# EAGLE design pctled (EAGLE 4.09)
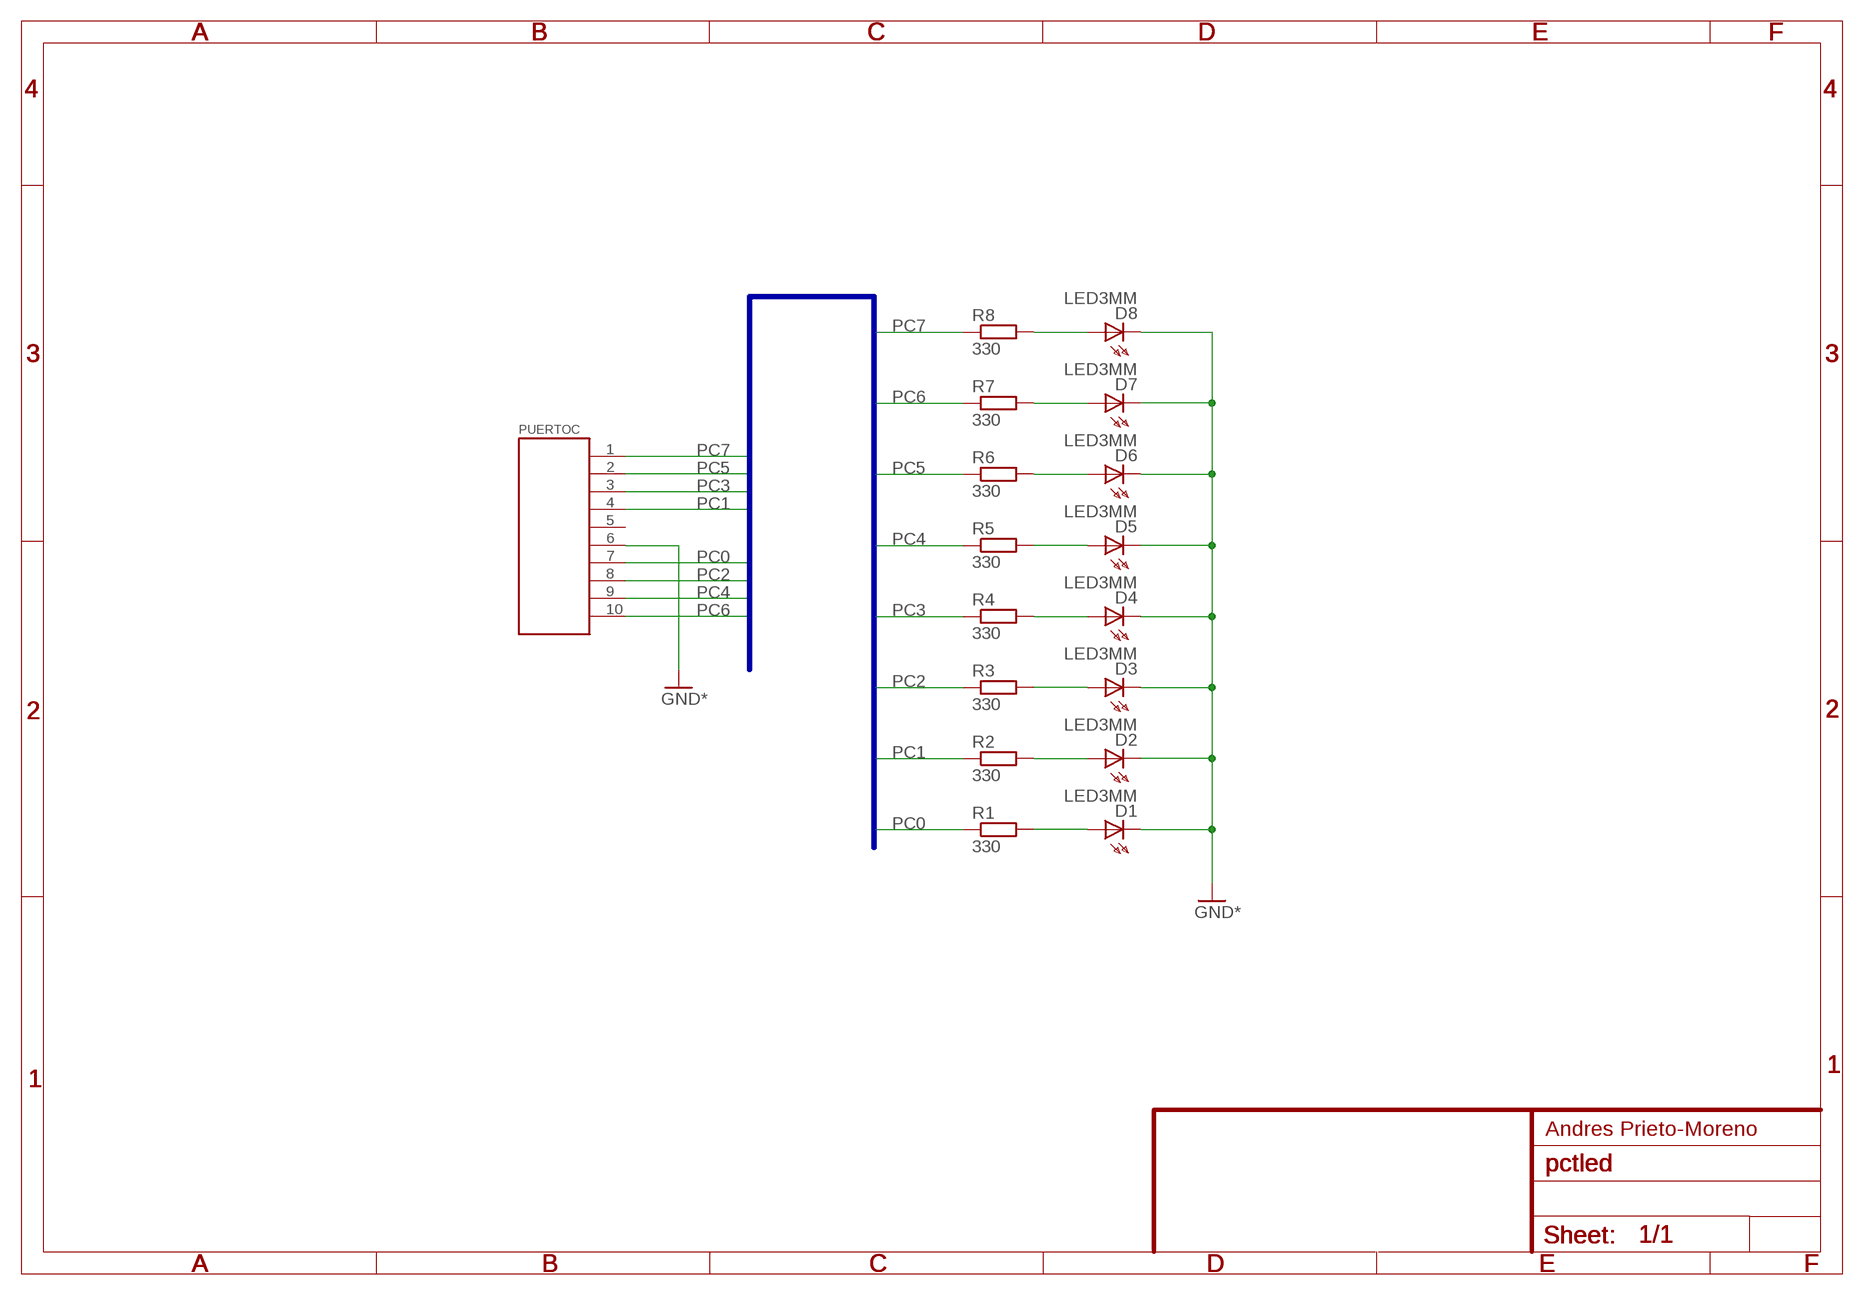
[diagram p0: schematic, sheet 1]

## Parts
D1  LED3MM  [LED3MM]
D2  LED3MM  [LED3MM]
D3  LED3MM  [LED3MM]
D4  LED3MM  [LED3MM]
D5  LED3MM  [LED3MM]
D6  LED3MM  [LED3MM]
D7  LED3MM  [LED3MM]
D8  LED3MM  [LED3MM]
PUERTOC  CTCONCTCON  [CTCON]
R1  330  R-EU_0207/10  [0207/10]
R2  330  R-EU_0207/10  [0207/10]
R3  330  R-EU_0207/10  [0207/10]
R4  330  R-EU_0207/10  [0207/10]
R5  330  R-EU_0207/10  [0207/10]
R6  330  R-EU_0207/10  [0207/10]
R7  330  R-EU_0207/10  [0207/10]
R8  330  R-EU_0207/10  [0207/10]

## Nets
GND: D1.K(C) D2.K(C) D3.K(C) D4.K(C) D5.K(C) D6.K(C) D7.K(C) D8.K(C) PUERTOC.6 ; supply symbol labelled GND*
N$1: D8.A R8.2
N$2: D7.A R7.2
N$3: D6.A R6.2
N$4: D5.A R5.2
N$5: D4.A R4.2
N$6: D3.A R3.2
N$7: D2.A R2.2
N$8: D1.A R1.2
PC0: PUERTOC.7 R1.1
PC1: PUERTOC.4 R2.1
PC2: PUERTOC.8 R3.1
PC3: PUERTOC.3 R4.1
PC4: PUERTOC.9 R5.1
PC5: PUERTOC.2 R6.1
PC6: PUERTOC.10 R7.1
PC7: PUERTOC.1 R8.1
Unconnected: PUERTOC.5

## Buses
BUSC:PC[0..7]

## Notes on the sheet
- Andres Prieto-Moreno

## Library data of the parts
D1-D8 = led:LED3MM: LED
PUERTOC = custom:CTCON: Conector compatible CT
R1-R8 = rcl:R-EU_: RESISTOR, European symbol

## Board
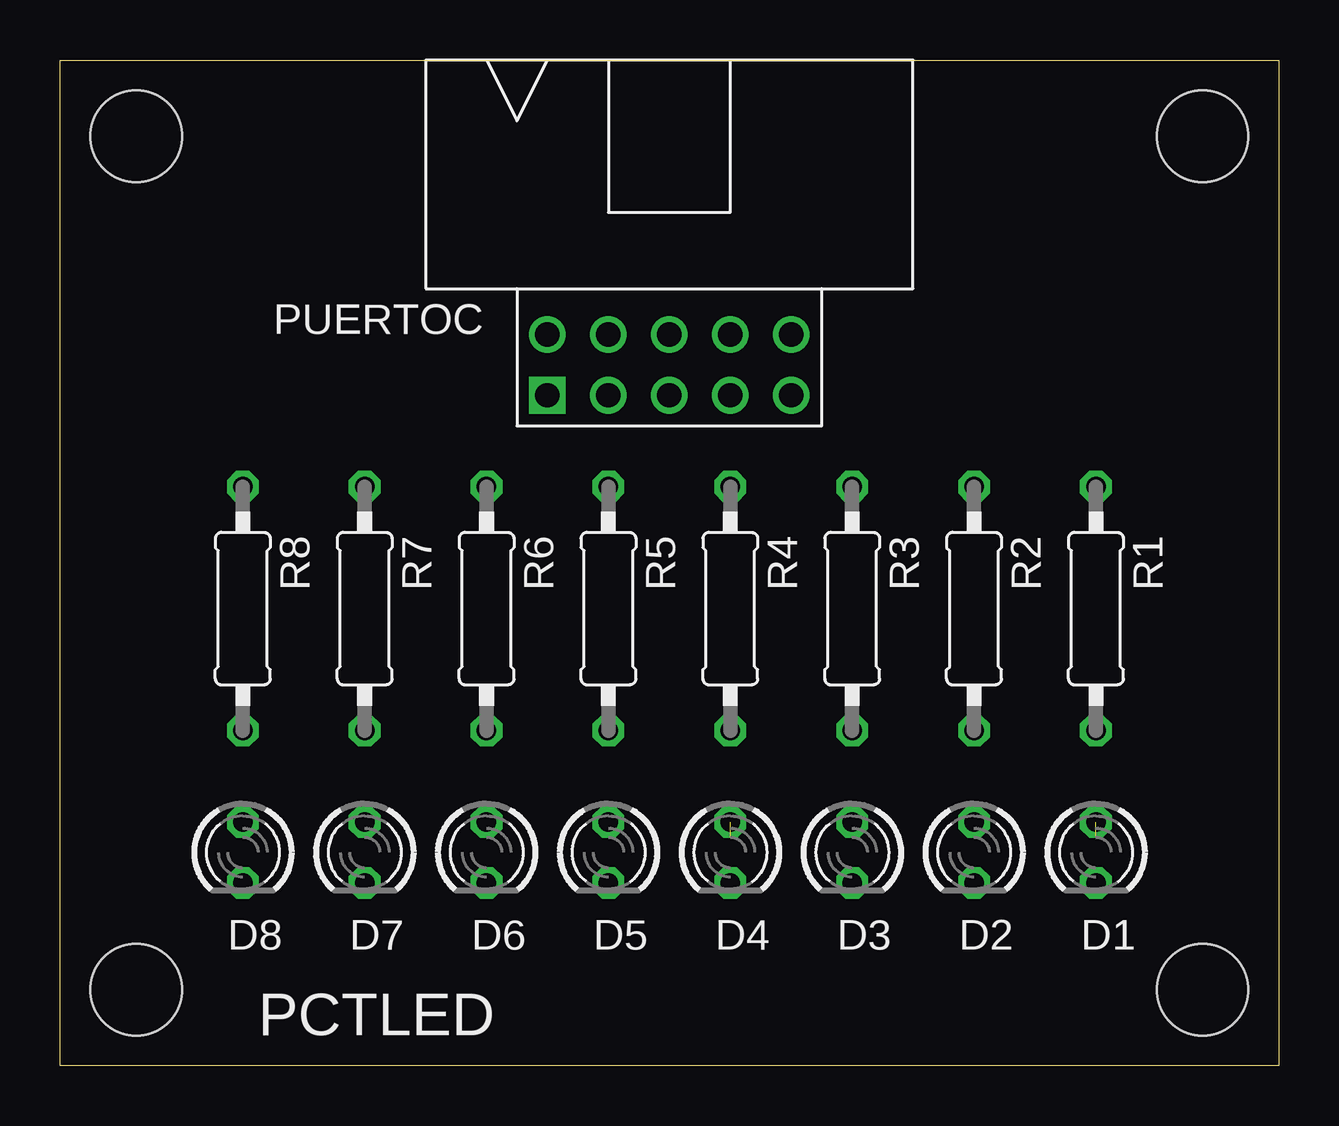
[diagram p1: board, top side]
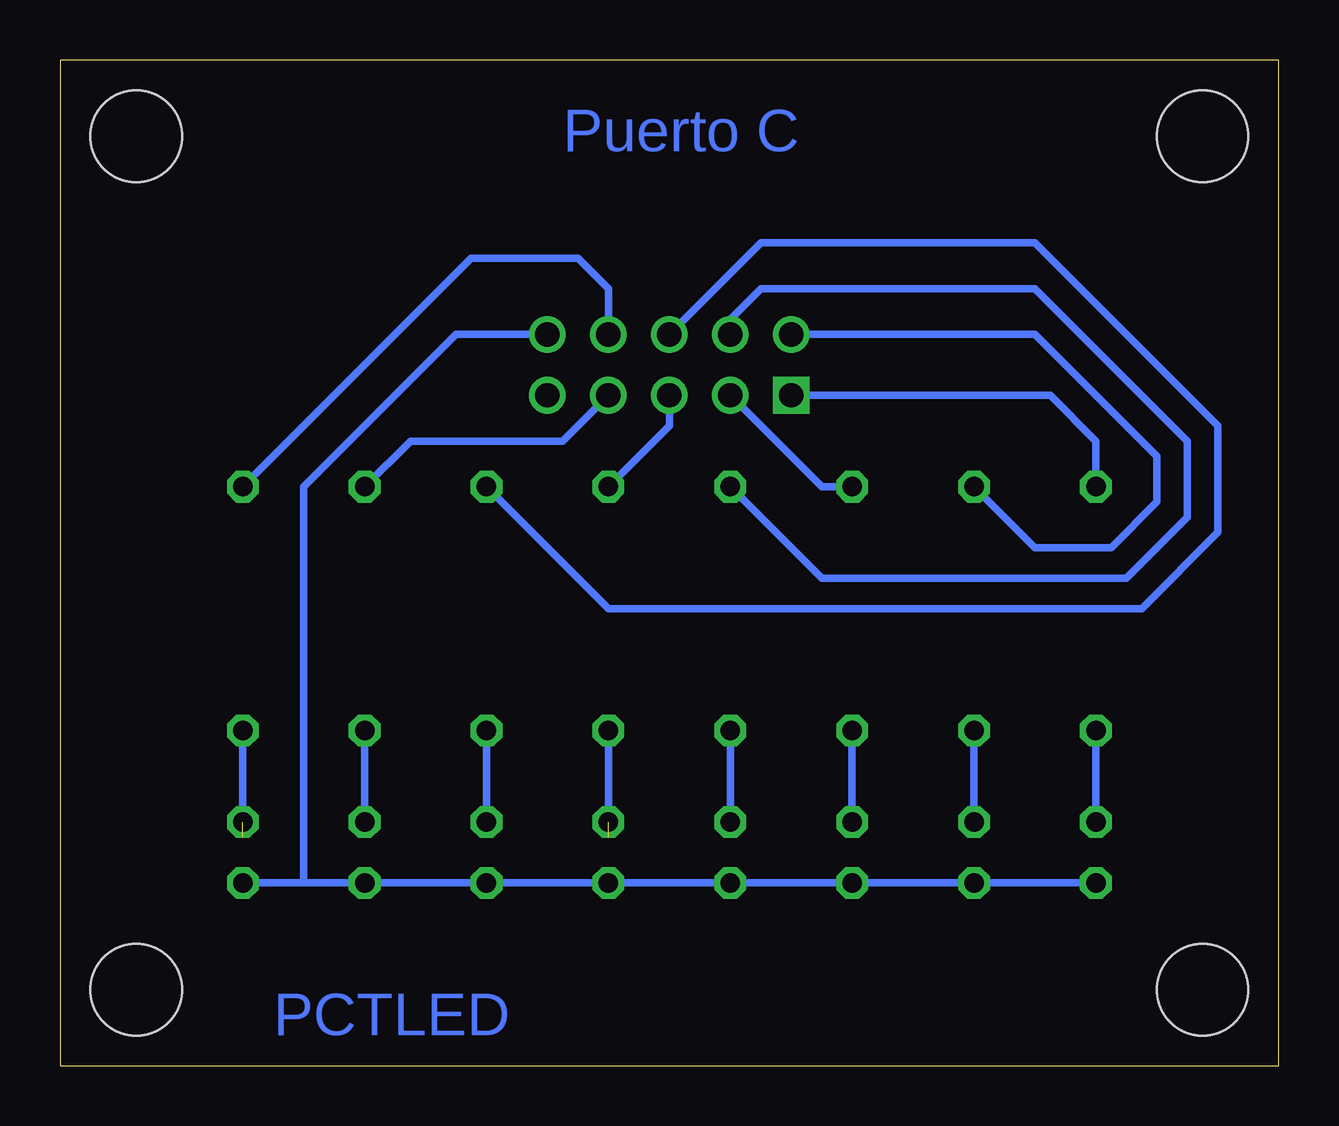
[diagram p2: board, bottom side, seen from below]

Size 50.8 x 41.91 mm. Coordinates in mm from the lower left corner, seen from the top.
Outline: 0,41.91 50.8,41.91 50.8,0 0,0 0,41.91
Copper layers used: Bottom
Holes 3.81 mm at 3.17,38.73 47.62,38.73 3.17,3.18 47.62,3.18

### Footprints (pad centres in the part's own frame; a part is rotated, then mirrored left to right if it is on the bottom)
LED3MM = drill 0.813 octagon: A -1.27,0; K 1.27,0
CTCON = drill 1.016 square: 1 0,0 | drill 1.016 round: 2 2.54,0; 3 5.08,0; 4 7.62,0; 5 10.16,0; 6 10.16,2.54; 7 7.62,2.54; 8 5.08,2.54; 9 2.54,2.54; 10 0,2.54
0207/10 = drill 0.813 octagon: 1 -5.08,0; 2 5.08,0

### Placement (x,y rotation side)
D1  43.18,8.89 270 top
D2  38.1,8.89 270 top
D3  33.02,8.89 270 top
D4  27.94,8.89 270 top
D5  22.86,8.89 270 top
D6  17.78,8.89 270 top
D7  12.7,8.89 270 top
D8  7.62,8.89 270 top
PUERTOC  20.32,27.94 0 top
R1  43.18,19.05 270 top
R2  38.1,19.05 270 top
R3  33.02,19.05 270 top
R4  27.94,19.05 270 top
R5  22.86,19.05 270 top
R6  17.78,19.05 270 top
R7  12.7,19.05 270 top
R8  7.62,19.05 270 top

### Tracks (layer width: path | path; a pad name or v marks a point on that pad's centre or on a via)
GND
  Bottom 0.305: PUERTOC.6 34.29,30.48 40.64,24.13 40.64,7.62 D2.K | D2.K D3.K | D1.K D2.K | D2.K D3.K | 32.38,7.62 D3.K | D3.K D4.K D5.K D6.K D7.K D8.K
N$1
  Bottom 0.305: D8.A R8.2
N$2
  Bottom 0.305: D7.A R7.2
N$3
  Bottom 0.305: D6.A R6.2
N$4
  Bottom 0.305: D5.A R5.2
N$5  (1 unrouted)
  Bottom 0.305: D4.A R4.2
N$6
  Bottom 0.305: D3.A R3.2
N$7
  Bottom 0.305: D2.A R2.2
N$8  (1 unrouted)
  Bottom 0.305: D1.A R1.2
PC0
  Bottom 0.305: PUERTOC.7 27.94,32.38 29.21,33.65 33.66,33.65 R1.1
PC1
  Bottom 0.305: PUERTOC.4 29.84,26.04 36.2,26.04 R2.1
PC2
  Bottom 0.305: PUERTOC.8 21.59,34.29 10.16,34.29 2.54,26.67 2.54,22.23 5.72,19.05 27.94,19.05 R3.1
PC3
  Bottom 0.305: PUERTOC.3 25.4,26.67 R4.1
PC4
  Bottom 0.305: PUERTOC.9 22.86,31.12 21.59,32.38 10.16,32.38 3.81,26.04 3.81,22.86 6.35,20.32 19.05,20.32 R5.1
PC5
  Bottom 0.305: PUERTOC.2 19.05,24.13 R6.1
PC6
  Bottom 0.305: PUERTOC.10 10.16,30.48 5.08,25.4 5.08,23.49 6.99,21.59 10.16,21.59 R7.1
PC7
  Bottom 0.305: PUERTOC.1 9.52,27.94 7.62,26.04 R8.1

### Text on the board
Bottom: Puerto C | PCTLED
tPlace: PCTLED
